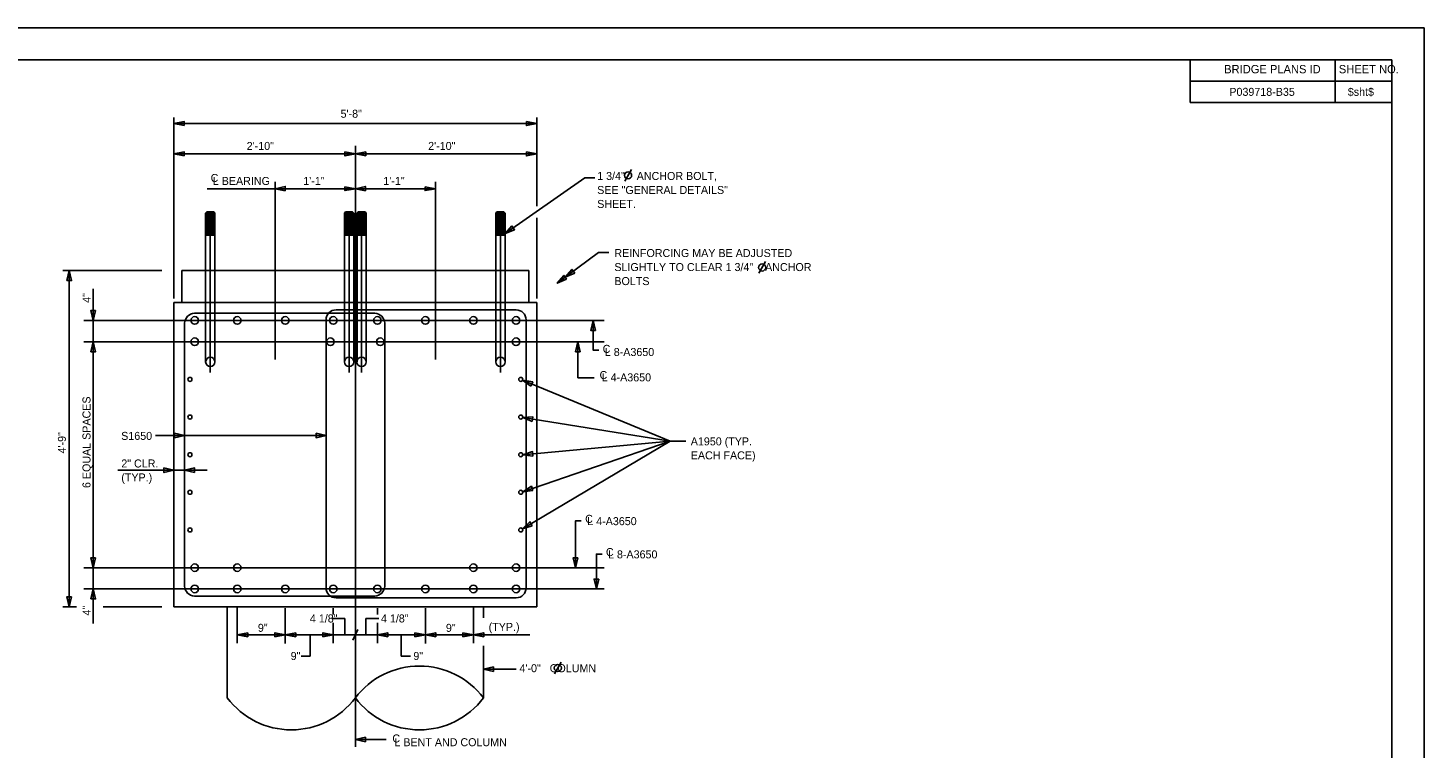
# Model space of a CAD drawing. Extents: x -133.1 to -97, y -1.7 to 20.3.
# Drawn here: x -118.94 to -97.14, y 9.06 to 20.31 of the extents above; entities that cross this region are included whole.
import ezdxf

# ---------------------------------------------------------------- set-up
doc = ezdxf.new("R2010")
doc.units = 0
for name, color, linetype in [('BR_AUTO DIMENSION', 7, 'Continuous'), ('BR_BORDER LINES', 7, 'Continuous'), ('BR_CENTER LINES', 7, 'Continuous'), ('BR_CONCRETE', 7, 'Continuous'), ('BR_REBAR', 7, 'Continuous'), ('BR_STRUCTURAL STEEL', 7, 'Continuous'), ('BR_TEXT', 7, 'Continuous'), ('Level 31', 7, 'Continuous')]:
    doc.layers.add(name, color=color, linetype=linetype)

msp = doc.modelspace()

# ---------------------------------------------------------------- linework, layer by layer
at = {"layer": 'BR_AUTO DIMENSION'}
for p, q in [((-116.664, 16.08), (-116.664, 18.909)), ((-116.664, 18.816), (-110.998, 18.816)), ((-110.998, 17.526), (-110.998, 18.909)), ((-116.664, 18.34), (-113.831, 18.34)), ((-113.831, 18.192), (-113.831, 18.468)), ((-110.998, 18.34), (-113.831, 18.34)), ((-111.493, 17.097), (-110.245, 17.967)), ((-110.245, 17.967), (-110.092, 17.967)), ((-116.145, 17.798), (-112.581, 17.798)), ((-110.998, 16.08), (-110.998, 17.345)), ((-116.851, 16.519), (-118.397, 16.519)), ((-118.299, 16.519), (-118.299, 11.268)), ((-117.924, 16.232), (-117.924, 11.006)), ((-110.355, 15.407), (-110.355, 14.845)), ((-110.355, 14.845), (-110.104, 14.845)), ((-108.917, 13.856), (-111.219, 14.806)), ((-108.917, 13.856), (-111.218, 14.222)), ((-114.289, 13.943), (-116.954, 13.943)), ((-108.917, 13.856), (-111.221, 12.483)), ((-108.917, 13.856), (-111.216, 13.64)), ((-116.146, 13.399), (-117.538, 13.399)), ((-118.186, 11.268), (-118.397, 11.268)), ((-116.851, 11.268), (-117.77, 11.268)), ((-115.675, 10.698), (-115.675, 11.249)), ((-114.925, 10.692), (-114.925, 11.244)), ((-114.175, 11.146), (-114.175, 11.246)), ((-113.487, 11.146), (-113.487, 11.246)), ((-112.737, 10.692), (-112.737, 11.244)), ((-111.987, 10.698), (-111.987, 11.249)), ((-113.993, 11.084), (-114.2, 11.084)), ((-114.175, 10.698), (-114.175, 11.016)), ((-113.993, 10.83), (-113.993, 11.084)), ((-113.868, 10.747), (-113.794, 10.912)), ((-113.668, 10.83), (-113.668, 11.084)), ((-113.668, 11.084), (-113.462, 11.084)), ((-113.487, 10.698), (-113.487, 11.016)), ((-111.105, 10.83), (-115.675, 10.83)), ((-114.535, 10.83), (-114.535, 10.498)), ((-113.113, 10.83), (-113.113, 10.498)), ((-114.535, 10.498), (-114.679, 10.498)), ((-113.113, 10.498), (-112.969, 10.498)), ((-111.831, 10.293), (-111.319, 10.293)), ((-113.831, 9.194), (-113.348, 9.194))]:
    msp.add_line(p, q, dxfattribs=at)
for points in [[(-116.502, 18.784), (-116.664, 18.816), (-116.502, 18.847)], [(-111.16, 18.847), (-110.998, 18.816), (-111.16, 18.784)], [(-116.502, 18.309), (-116.664, 18.34), (-116.502, 18.371)], [(-113.993, 18.371), (-113.831, 18.34), (-113.993, 18.309)], [(-113.668, 18.309), (-113.831, 18.34), (-113.668, 18.371)], [(-111.16, 18.371), (-110.998, 18.34), (-111.16, 18.309)], [(-114.925, 17.762), (-115.081, 17.798), (-114.925, 17.834)], [(-113.993, 17.829), (-113.831, 17.798), (-113.993, 17.767)], [(-113.675, 17.762), (-113.831, 17.798), (-113.675, 17.834)], [(-112.743, 17.829), (-112.581, 17.798), (-112.743, 17.767)], [(-111.386, 17.216), (-111.493, 17.097), (-111.345, 17.157)], [(-118.335, 16.363), (-118.299, 16.519), (-118.263, 16.363)], [(-110.531, 16.385), (-110.677, 16.32), (-110.574, 16.442)], [(-110.406, 16.478), (-110.552, 16.414), (-110.449, 16.536)], [(-117.888, 15.896), (-117.924, 15.74), (-117.96, 15.896)], [(-110.082, 15.584), (-110.118, 15.74), (-110.154, 15.584)], [(-117.96, 15.251), (-117.924, 15.407), (-117.888, 15.251)], [(-110.319, 15.251), (-110.355, 15.407), (-110.391, 15.251)], [(-111.088, 14.714), (-111.219, 14.806), (-111.061, 14.78)], [(-111.069, 14.161), (-111.218, 14.222), (-111.058, 14.233)], [(-116.653, 13.979), (-116.498, 13.943), (-116.653, 13.907)], [(-114.445, 13.979), (-114.289, 13.943), (-114.445, 13.907)], [(-111.058, 13.619), (-111.216, 13.64), (-111.064, 13.691)], [(-116.82, 13.435), (-116.664, 13.399), (-116.82, 13.363)], [(-116.342, 13.363), (-116.498, 13.399), (-116.342, 13.435)], [(-111.059, 13.082), (-111.218, 13.065), (-111.082, 13.15)], [(-111.069, 12.532), (-111.221, 12.483), (-111.106, 12.594)], [(-117.888, 12.034), (-117.924, 11.878), (-117.96, 12.034)], [(-110.355, 12.034), (-110.391, 11.878), (-110.427, 12.034)], [(-110.031, 11.701), (-110.067, 11.545), (-110.103, 11.701)], [(-118.263, 11.424), (-118.299, 11.268), (-118.335, 11.424)], [(-117.96, 11.389), (-117.924, 11.545), (-117.888, 11.389)], [(-115.512, 10.861), (-115.675, 10.83), (-115.512, 10.799)], [(-115.087, 10.799), (-114.925, 10.83), (-115.087, 10.861)], [(-114.762, 10.861), (-114.925, 10.83), (-114.762, 10.799)], [(-114.337, 10.799), (-114.175, 10.83), (-114.337, 10.861)], [(-113.325, 10.799), (-113.487, 10.83), (-113.325, 10.861)], [(-112.9, 10.861), (-112.737, 10.83), (-112.9, 10.799)], [(-112.575, 10.799), (-112.737, 10.83), (-112.575, 10.861)], [(-112.15, 10.861), (-111.987, 10.83), (-112.15, 10.799)], [(-111.825, 10.799), (-111.987, 10.83), (-111.825, 10.861)], [(-111.675, 10.257), (-111.831, 10.293), (-111.675, 10.329)], [(-113.675, 9.158), (-113.831, 9.194), (-113.675, 9.23)]]:
    msp.add_lwpolyline(points, close=True, dxfattribs=at)
for points in [[(-110.677, 16.32), (-110.036, 16.799), (-109.871, 16.799)], [(-110.118, 15.74), (-110.118, 15.277), (-110.03, 15.277)], [(-111.218, 13.065), (-108.917, 13.856), (-108.669, 13.856)], [(-110.391, 11.878), (-110.391, 12.611), (-110.303, 12.611)], [(-110.067, 11.545), (-110.067, 12.091), (-109.979, 12.091)]]:
    msp.add_lwpolyline(points, dxfattribs=at)
at = {"layer": 'BR_BORDER LINES'}
for p, q in [((-97.642, 19.809), (-131.308, 19.809)), ((-100.794, 19.142), (-100.794, 19.809)), ((-98.528, 19.142), (-98.528, 19.809)), ((-97.642, -1.191), (-97.642, 19.809)), ((-100.794, 19.479), (-97.642, 19.479)), ((-98.528, 19.479), (-97.642, 19.479)), ((-97.642, 19.142), (-100.794, 19.142))]:
    msp.add_line(p, q, dxfattribs=at)
at = {"layer": 'BR_CENTER LINES'}
for p, q in [((-113.831, 18.192), (-113.831, 9.079)), ((-115.081, 17.905), (-115.081, 15.128)), ((-112.581, 17.905), (-112.581, 15.128)), ((-116.096, 14.925), (-116.096, 17.224)), ((-113.929, 14.925), (-113.929, 17.224)), ((-113.733, 14.925), (-113.733, 17.224)), ((-111.566, 14.925), (-111.566, 17.224)), ((-118.072, 15.74), (-109.944, 15.74)), ((-118.072, 15.407), (-109.944, 15.407)), ((-118.072, 11.878), (-109.944, 11.878)), ((-118.072, 11.545), (-109.944, 11.545))]:
    msp.add_line(p, q, dxfattribs=at)
at = {"layer": 'BR_CONCRETE'}
for p, q in [((-116.539, 16.519), (-116.539, 16.018)), ((-116.539, 16.519), (-111.123, 16.519)), ((-111.123, 16.519), (-111.123, 16.018)), ((-116.664, 16.018), (-116.664, 11.268)), ((-116.664, 16.018), (-110.998, 16.018)), ((-110.998, 16.018), (-110.998, 11.268)), ((-116.664, 11.268), (-110.998, 11.268)), ((-115.831, 11.268), (-115.831, 9.843)), ((-111.831, 11.268), (-111.831, 11.095)), ((-111.831, 10.656), (-111.831, 9.843))]:
    msp.add_line(p, q, dxfattribs=at)
for centre, start, end in [((-112.831, 9.09), 37.0023, 142.9977), ((-114.831, 10.597), 217.0023, 322.9977), ((-112.831, 10.597), 217.0023, 322.9977)]:
    msp.add_arc(centre, 1.252, start, end, dxfattribs=at)
at = {"layer": 'BR_REBAR'}
for p, q in [((-116.344, 15.851), (-113.529, 15.851)), ((-114.289, 15.749), (-114.289, 11.563)), ((-111.318, 15.905), (-114.133, 15.905)), ((-111.164, 15.747), (-111.164, 11.561)), ((-116.498, 15.697), (-116.498, 11.588)), ((-113.372, 15.695), (-113.372, 11.591)), ((-116.344, 11.434), (-113.529, 11.434)), ((-111.318, 11.407), (-114.133, 11.407))]:
    msp.add_line(p, q, dxfattribs=at)
for centre, radius in [((-116.339, 15.74), 0.0588), ((-115.675, 15.74), 0.0588), ((-114.925, 15.74), 0.0588), ((-114.175, 15.74), 0.0588), ((-113.487, 15.74), 0.0588), ((-112.737, 15.74), 0.0588), ((-111.987, 15.74), 0.0588), ((-111.322, 15.74), 0.0588), ((-116.339, 15.407), 0.0588), ((-114.22, 15.407), 0.0588), ((-113.442, 15.407), 0.0588), ((-111.322, 15.407), 0.0588), ((-116.414, 14.819), 0.0313), ((-111.248, 14.819), 0.0313), ((-116.414, 14.231), 0.0313), ((-111.248, 14.231), 0.0313), ((-116.414, 13.643), 0.0313), ((-111.248, 13.643), 0.0313), ((-116.414, 13.055), 0.0313), ((-111.248, 13.055), 0.0313), ((-116.414, 12.467), 0.0313), ((-111.248, 12.467), 0.0313), ((-116.339, 11.878), 0.0588), ((-115.675, 11.878), 0.0588), ((-111.987, 11.878), 0.0588), ((-111.322, 11.878), 0.0588), ((-116.339, 11.545), 0.0588), ((-115.675, 11.545), 0.0588), ((-114.925, 11.545), 0.0588), ((-114.175, 11.545), 0.0588), ((-113.487, 11.545), 0.0588), ((-112.737, 11.545), 0.0588), ((-111.987, 11.545), 0.0588), ((-111.322, 11.545), 0.0588)]:
    msp.add_circle(centre, radius, dxfattribs=at)
for centre, start, end in [((-116.341, 15.695), 91.025, 178.975), ((-114.133, 15.749), 90, 180), ((-113.529, 15.695), 0, 90), ((-111.32, 15.749), 1.025, 88.975), ((-116.341, 11.591), 181.025, 268.975), ((-114.133, 11.563), 180, 270), ((-113.529, 11.591), 270, 0), ((-111.32, 11.563), 271.025, 358.975)]:
    msp.add_arc(centre, 0.156, start, end, dxfattribs=at)
at = {"layer": 'BR_STRUCTURAL STEEL'}
for p, q in [((-116.169, 17.417), (-116.151, 17.436)), ((-116.169, 17.417), (-116.023, 17.417)), ((-116.169, 17.417), (-116.169, 16.519)), ((-116.169, 17.399), (-116.023, 17.399)), ((-116.169, 17.381), (-116.023, 17.381)), ((-116.169, 17.363), (-116.023, 17.363)), ((-116.169, 17.344), (-116.023, 17.344)), ((-116.169, 17.326), (-116.023, 17.326)), ((-116.169, 17.308), (-116.023, 17.308)), ((-116.169, 17.29), (-116.023, 17.29)), ((-116.169, 17.271), (-116.023, 17.271)), ((-116.169, 17.253), (-116.023, 17.253)), ((-116.169, 17.235), (-116.023, 17.235)), ((-116.151, 17.436), (-116.041, 17.436)), ((-116.041, 17.436), (-116.023, 17.417)), ((-116.023, 17.417), (-116.023, 16.519)), ((-114.002, 17.417), (-113.984, 17.436)), ((-114.002, 17.417), (-113.856, 17.417)), ((-114.002, 17.417), (-114.002, 16.519)), ((-114.002, 17.399), (-113.856, 17.399)), ((-114.002, 17.381), (-113.856, 17.381)), ((-114.002, 17.363), (-113.856, 17.363)), ((-114.002, 17.344), (-113.856, 17.344)), ((-114.002, 17.326), (-113.856, 17.326)), ((-114.002, 17.308), (-113.856, 17.308)), ((-114.002, 17.29), (-113.856, 17.29)), ((-114.002, 17.271), (-113.856, 17.271)), ((-114.002, 17.253), (-113.856, 17.253)), ((-114.002, 17.235), (-113.856, 17.235)), ((-113.984, 17.436), (-113.875, 17.436)), ((-113.875, 17.436), (-113.856, 17.417)), ((-113.856, 17.417), (-113.856, 16.519)), ((-113.805, 17.417), (-113.787, 17.436)), ((-113.805, 17.417), (-113.66, 17.417)), ((-113.805, 17.417), (-113.805, 16.519)), ((-113.805, 17.399), (-113.66, 17.399)), ((-113.805, 17.381), (-113.66, 17.381)), ((-113.805, 17.363), (-113.66, 17.363)), ((-113.805, 17.344), (-113.66, 17.344)), ((-113.805, 17.326), (-113.66, 17.326)), ((-113.805, 17.308), (-113.66, 17.308)), ((-113.805, 17.29), (-113.66, 17.29)), ((-113.805, 17.271), (-113.66, 17.271)), ((-113.805, 17.253), (-113.66, 17.253)), ((-113.805, 17.235), (-113.66, 17.235)), ((-113.787, 17.436), (-113.678, 17.436)), ((-113.678, 17.436), (-113.66, 17.417)), ((-113.66, 17.417), (-113.66, 16.519)), ((-111.639, 17.417), (-111.621, 17.436)), ((-111.639, 17.417), (-111.493, 17.417)), ((-111.639, 17.417), (-111.639, 16.519)), ((-111.639, 17.399), (-111.493, 17.399)), ((-111.639, 17.381), (-111.493, 17.381)), ((-111.639, 17.363), (-111.493, 17.363)), ((-111.639, 17.344), (-111.493, 17.344)), ((-111.639, 17.326), (-111.493, 17.326)), ((-111.639, 17.308), (-111.493, 17.308)), ((-111.639, 17.29), (-111.493, 17.29)), ((-111.639, 17.271), (-111.493, 17.271)), ((-111.639, 17.253), (-111.493, 17.253)), ((-111.639, 17.235), (-111.493, 17.235)), ((-111.621, 17.436), (-111.511, 17.436)), ((-111.511, 17.436), (-111.493, 17.417)), ((-111.493, 17.417), (-111.493, 16.519)), ((-116.169, 17.217), (-116.023, 17.217)), ((-116.169, 17.199), (-116.023, 17.199)), ((-116.169, 17.18), (-116.023, 17.18)), ((-116.169, 17.162), (-116.023, 17.162)), ((-116.169, 17.144), (-116.023, 17.144)), ((-116.169, 17.126), (-116.023, 17.126)), ((-116.169, 17.107), (-116.023, 17.107)), ((-116.169, 17.089), (-116.023, 17.089)), ((-116.169, 17.071), (-116.023, 17.071)), ((-114.002, 17.217), (-113.856, 17.217)), ((-114.002, 17.199), (-113.856, 17.199)), ((-114.002, 17.18), (-113.856, 17.18)), ((-114.002, 17.162), (-113.856, 17.162)), ((-114.002, 17.144), (-113.856, 17.144)), ((-114.002, 17.126), (-113.856, 17.126)), ((-114.002, 17.107), (-113.856, 17.107)), ((-114.002, 17.089), (-113.856, 17.089)), ((-114.002, 17.071), (-113.856, 17.071)), ((-113.805, 17.217), (-113.66, 17.217)), ((-113.805, 17.199), (-113.66, 17.199)), ((-113.805, 17.18), (-113.66, 17.18)), ((-113.805, 17.162), (-113.66, 17.162)), ((-113.805, 17.144), (-113.66, 17.144)), ((-113.805, 17.126), (-113.66, 17.126)), ((-113.805, 17.107), (-113.66, 17.107)), ((-113.805, 17.089), (-113.66, 17.089)), ((-113.805, 17.071), (-113.66, 17.071)), ((-111.639, 17.217), (-111.493, 17.217)), ((-111.639, 17.199), (-111.493, 17.199)), ((-111.639, 17.18), (-111.493, 17.18)), ((-111.639, 17.162), (-111.493, 17.162)), ((-111.639, 17.144), (-111.493, 17.144)), ((-111.639, 17.126), (-111.493, 17.126)), ((-111.639, 17.107), (-111.493, 17.107)), ((-111.639, 17.089), (-111.493, 17.089)), ((-111.639, 17.071), (-111.493, 17.071)), ((-116.169, 16.519), (-116.169, 15.094)), ((-116.023, 16.519), (-116.023, 15.092)), ((-114.002, 16.519), (-114.002, 15.094)), ((-113.856, 16.519), (-113.856, 15.092)), ((-113.805, 16.519), (-113.805, 15.094)), ((-113.66, 16.519), (-113.66, 15.092)), ((-111.639, 16.519), (-111.639, 15.094)), ((-111.493, 16.519), (-111.493, 15.092))]:
    msp.add_line(p, q, dxfattribs=at)
for centre in [(-116.096, 15.092), (-113.929, 15.092), (-113.733, 15.092), (-111.566, 15.092)]:
    msp.add_circle(centre, 0.0729, dxfattribs=at)
at = {"layer": 'BR_TEXT'}
for p, q in [((-109.624, 17.914), (-109.519, 18.096)), ((-107.53, 16.477), (-107.425, 16.658)), ((-118.299, 11.268), (-118.299, 11.415)), ((-110.721, 10.22), (-110.616, 10.402))]:
    msp.add_line(p, q, dxfattribs=at)
for centre in [(-109.571, 18.005), (-107.478, 16.567), (-110.669, 10.311)]:
    msp.add_circle(centre, 0.055, dxfattribs=at)
at = {"layer": 'Level 31'}
msp.add_lwpolyline([(-133.141, -1.691), (-97.141, -1.691), (-97.141, 20.309), (-133.141, 20.309)], close=True, dxfattribs=at)

# ---------------------------------------------------------------- texts
at = {"layer": 'BR_AUTO DIMENSION'}
for s, p in [('5\'-8"', (-114.062, 18.906)), ('2\'-10"', (-115.528, 18.403)), ('2\'-10"', (-112.694, 18.403))]:
    msp.add_text(s, height=0.125, dxfattribs=at).set_placement(p)
at = {"layer": 'BR_TEXT'}
for s, height, p in [('BRIDGE PLANS ID', 0.13, (-100.263, 19.6)), ('SHEET NO.', 0.13, (-98.472, 19.6)), ('P039718-B35', 0.125, (-100.182, 19.248)), ('$sht$', 0.125, (-98.332, 19.248)), ('4 1/8"', 0.125, (-114.541, 11.022)), ('4 1/8"', 0.125, (-113.431, 11.022))]:
    msp.add_text(s, height=height, dxfattribs=at).set_placement(p)
for s, rotation, p in [('C', 360, (-116.091, 17.903)), ('L BEARING', 360, (-116.057, 17.856)), ('1\'-1"', 360, (-114.644, 17.856)), ('1\'-1"', 360, (-113.394, 17.856)), ('1 3/4"    ANCHOR BOLT, ', 360, (-110.054, 17.934)), ('SEE "GENERAL DETAILS"', 360, (-110.054, 17.715)), ('SHEET.', 360, (-110.054, 17.497)), ('REINFORCING MAY BE ADJUSTED', 360, (-109.786, 16.73)), ('SLIGHTLY TO CLEAR 1 3/4"    ANCHOR', 360, (-109.786, 16.511)), ('BOLTS', 360, (-109.786, 16.292)), ('4"', 90, (-117.967, 16.015)), ('C', 360, (-109.969, 15.233)), ('L 8-A3650', 360, (-109.935, 15.184)), ('C', 360, (-110.017, 14.824)), ('L 4-A3650', 360, (-109.984, 14.788)), ('6 EQUAL SPACES', 90, (-117.967, 13.122)), ('4\'-9"', 90, (-118.351, 13.662)), ('S1650', 360, (-117.488, 13.874)), ('A1950 (TYP.', 360, (-108.593, 13.788)), ('2" CLR.', 360, (-117.486, 13.443)), ('EACH FACE)', 360, (-108.593, 13.57)), ('(TYP.)', 360, (-117.486, 13.225)), ('C', 360, (-110.242, 12.578)), ('L 4-A3650', 360, (-110.209, 12.542)), ('C', 360, (-109.918, 12.059)), ('L 8-A3650', 360, (-109.885, 12.023)), ('4"', 90, (-117.967, 11.131)), ('9"', 360, (-115.353, 10.876)), ('9"', 360, (-112.417, 10.875)), ('(TYP.)', 360, (-111.749, 10.891)), ('9"', 360, (-114.841, 10.436)), ('9"', 360, (-112.925, 10.436)), ('4\'-0"   COLUMN', 360, (-111.268, 10.245)), ('C', 360, (-113.253, 9.148)), ('L BENT AND COLUMN', 360, (-113.221, 9.089))]:
    msp.add_text(s, height=0.125, rotation=rotation, dxfattribs=at).set_placement(p)

doc.saveas('drawing.dxf')
